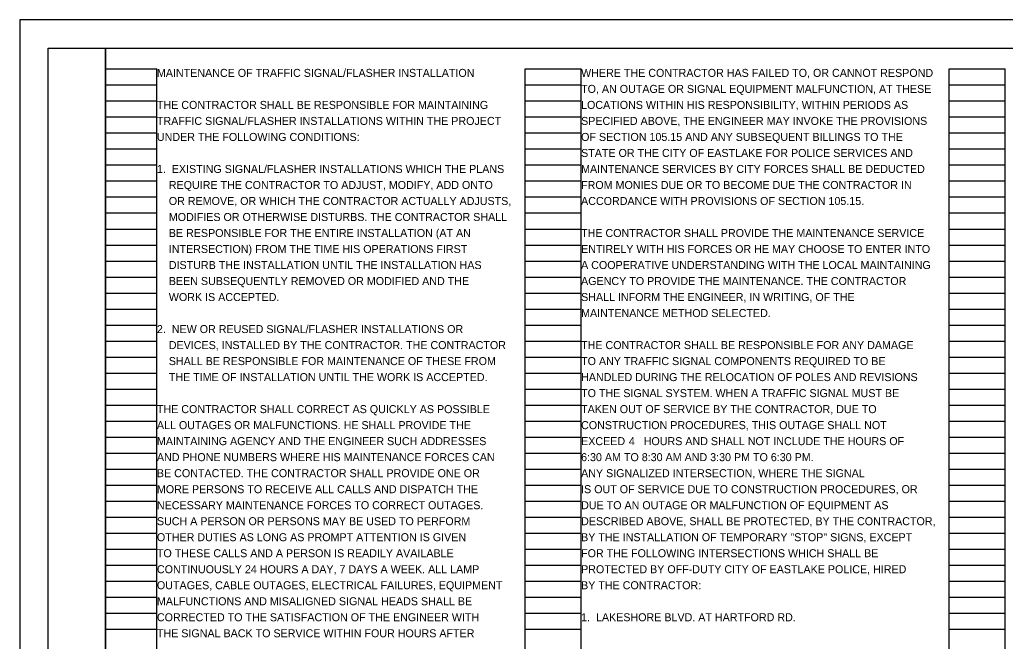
# Model space of a CAD drawing. Extents: x 0 to 34, y 0 to 22.
# Drawn here: x 0 to 17.24, y 11.13 to 22 of the extents above; entities that cross this region are included whole.
import ezdxf

# ---------------------------------------------------------------- set-up
doc = ezdxf.new("R2010")
doc.units = 0
for name, color, linetype in [('SH_Border', 7, 'Continuous'), ('SH_Cut_Line', 7, 'Continuous'), ('SH_Data', 7, 'Continuous'), ('SH_Text', 7, 'Continuous')]:
    doc.layers.add(name, color=color, linetype=linetype)

msp = doc.modelspace()

# ---------------------------------------------------------------- linework, layer by layer
at = {"layer": 'SH_Border'}
for points in [[(0.5, 21.5), (1.5, 21.5), (1.5, 0.5), (0.5, 0.5)], [(1.5, 21.5), (33.5, 21.5), (33.5, 0.5), (1.5, 0.5)]]:
    msp.add_lwpolyline(points, close=True, dxfattribs=at)
at = {"layer": 'SH_Cut_Line'}
msp.add_lwpolyline([(0, 0), (34, 0), (34, 22), (0, 22)], close=True, dxfattribs=at)
at = {"layer": 'SH_Data'}
for p, q in [((1.5, 0.98), (1.5, 21.14)), ((1.5, 21.14), (2.4, 21.14)), ((2.4, 0.98), (2.4, 21.14)), ((8.84, 0.98), (8.84, 21.14)), ((8.84, 21.14), (9.82, 21.14)), ((9.82, 0.98), (9.82, 21.14)), ((16.26, 0.98), (16.26, 21.14)), ((16.26, 21.14), (17.24, 21.14)), ((17.24, 0.98), (17.24, 21.14)), ((1.5, 20.86), (2.4, 20.86)), ((8.84, 20.86), (9.82, 20.86)), ((16.26, 20.86), (17.24, 20.86)), ((1.5, 20.58), (2.4, 20.58)), ((8.84, 20.58), (9.82, 20.58)), ((16.26, 20.58), (17.24, 20.58)), ((1.5, 20.3), (2.4, 20.3)), ((8.84, 20.3), (9.82, 20.3)), ((16.26, 20.3), (17.24, 20.3)), ((1.5, 20.02), (2.4, 20.02)), ((8.84, 20.02), (9.82, 20.02)), ((16.26, 20.02), (17.24, 20.02)), ((1.5, 19.74), (2.4, 19.74)), ((8.84, 19.74), (9.82, 19.74)), ((16.26, 19.74), (17.24, 19.74)), ((1.5, 19.46), (2.4, 19.46)), ((8.84, 19.46), (9.82, 19.46)), ((16.26, 19.46), (17.24, 19.46)), ((1.5, 19.18), (2.4, 19.18)), ((8.84, 19.18), (9.82, 19.18)), ((16.26, 19.18), (17.24, 19.18)), ((1.5, 18.9), (2.4, 18.9)), ((8.84, 18.9), (9.82, 18.9)), ((16.26, 18.9), (17.24, 18.9)), ((1.5, 18.62), (2.4, 18.62)), ((8.84, 18.62), (9.82, 18.62)), ((16.26, 18.62), (17.24, 18.62)), ((1.5, 18.34), (2.4, 18.34)), ((8.84, 18.34), (9.82, 18.34)), ((16.26, 18.34), (17.24, 18.34)), ((1.5, 18.06), (2.4, 18.06)), ((8.84, 18.06), (9.82, 18.06)), ((16.26, 18.06), (17.24, 18.06)), ((1.5, 17.78), (2.4, 17.78)), ((8.84, 17.78), (9.82, 17.78)), ((16.26, 17.78), (17.24, 17.78)), ((1.5, 17.5), (2.4, 17.5)), ((8.84, 17.5), (9.82, 17.5)), ((16.26, 17.5), (17.24, 17.5)), ((1.5, 17.22), (2.4, 17.22)), ((8.84, 17.22), (9.82, 17.22)), ((16.26, 17.22), (17.24, 17.22)), ((1.5, 16.94), (2.4, 16.94)), ((8.84, 16.94), (9.82, 16.94)), ((16.26, 16.94), (17.24, 16.94)), ((1.5, 16.66), (2.4, 16.66)), ((8.84, 16.66), (9.82, 16.66)), ((16.26, 16.66), (17.24, 16.66)), ((1.5, 16.38), (2.4, 16.38)), ((8.84, 16.38), (9.82, 16.38)), ((16.26, 16.38), (17.24, 16.38)), ((1.5, 16.1), (2.4, 16.1)), ((8.84, 16.1), (9.82, 16.1)), ((16.26, 16.1), (17.24, 16.1)), ((1.5, 15.82), (2.4, 15.82)), ((8.84, 15.82), (9.82, 15.82)), ((16.26, 15.82), (17.24, 15.82)), ((1.5, 15.54), (2.4, 15.54)), ((8.84, 15.54), (9.82, 15.54)), ((16.26, 15.54), (17.24, 15.54)), ((1.5, 15.26), (2.4, 15.26)), ((8.84, 15.26), (9.82, 15.26)), ((16.26, 15.26), (17.24, 15.26)), ((1.5, 14.98), (2.4, 14.98)), ((8.84, 14.98), (9.82, 14.98)), ((16.26, 14.98), (17.24, 14.98)), ((1.5, 14.7), (2.4, 14.7)), ((8.84, 14.7), (9.82, 14.7)), ((16.26, 14.7), (17.24, 14.7)), ((1.5, 14.42), (2.4, 14.42)), ((8.84, 14.42), (9.82, 14.42)), ((16.26, 14.42), (17.24, 14.42)), ((1.5, 14.14), (2.4, 14.14)), ((8.84, 14.14), (9.82, 14.14)), ((16.26, 14.14), (17.24, 14.14)), ((1.5, 13.86), (2.4, 13.86)), ((8.84, 13.86), (9.82, 13.86)), ((16.26, 13.86), (17.24, 13.86)), ((1.5, 13.58), (2.4, 13.58)), ((8.84, 13.58), (9.82, 13.58)), ((16.26, 13.58), (17.24, 13.58)), ((1.5, 13.3), (2.4, 13.3)), ((8.84, 13.3), (9.82, 13.3)), ((16.26, 13.3), (17.24, 13.3)), ((1.5, 13.02), (2.4, 13.02)), ((8.84, 13.02), (9.82, 13.02)), ((16.26, 13.02), (17.24, 13.02)), ((1.5, 12.74), (2.4, 12.74)), ((8.84, 12.74), (9.82, 12.74)), ((16.26, 12.74), (17.24, 12.74)), ((1.5, 12.46), (2.4, 12.46)), ((8.84, 12.46), (9.82, 12.46)), ((16.26, 12.46), (17.24, 12.46)), ((1.5, 12.18), (2.4, 12.18)), ((8.84, 12.18), (9.82, 12.18)), ((16.26, 12.18), (17.24, 12.18)), ((1.5, 11.9), (2.4, 11.9)), ((8.84, 11.9), (9.82, 11.9)), ((16.26, 11.9), (17.24, 11.9)), ((1.5, 11.62), (2.4, 11.62)), ((8.84, 11.62), (9.82, 11.62)), ((16.26, 11.62), (17.24, 11.62)), ((1.5, 11.34), (2.4, 11.34)), ((8.84, 11.34), (9.82, 11.34)), ((16.26, 11.34), (17.24, 11.34))]:
    msp.add_line(p, q, dxfattribs=at)

# ---------------------------------------------------------------- texts
at = {"layer": 'SH_Text'}
for s, p in [('MAINTENANCE OF TRAFFIC SIGNAL/FLASHER INSTALLATION', (2.4, 21)), ('WHERE THE CONTRACTOR HAS FAILED TO, OR CANNOT RESPOND', (9.82, 21)), ('TO, AN OUTAGE OR SIGNAL EQUIPMENT MALFUNCTION, AT THESE', (9.82, 20.72)), ('THE CONTRACTOR SHALL BE RESPONSIBLE FOR MAINTAINING', (2.4, 20.44)), ('LOCATIONS WITHIN HIS RESPONSIBILITY, WITHIN PERIODS AS', (9.82, 20.44)), ('TRAFFIC SIGNAL/FLASHER INSTALLATIONS WITHIN THE PROJECT', (2.4, 20.16)), ('SPECIFIED ABOVE, THE ENGINEER MAY INVOKE THE PROVISIONS', (9.82, 20.16)), ('UNDER THE FOLLOWING CONDITIONS:', (2.4, 19.88)), ('OF SECTION 105.15 AND ANY SUBSEQUENT BILLINGS TO THE', (9.82, 19.88)), ('STATE OR THE CITY OF EASTLAKE FOR POLICE SERVICES AND', (9.82, 19.6)), ('1.  EXISTING SIGNAL/FLASHER INSTALLATIONS WHICH THE PLANS', (2.4, 19.32)), ('MAINTENANCE SERVICES BY CITY FORCES SHALL BE DEDUCTED', (9.82, 19.32)), ('    REQUIRE THE CONTRACTOR TO ADJUST, MODIFY, ADD ONTO', (2.4, 19.04)), ('FROM MONIES DUE OR TO BECOME DUE THE CONTRACTOR IN', (9.82, 19.04)), ('    OR REMOVE, OR WHICH THE CONTRACTOR ACTUALLY ADJUSTS,', (2.4, 18.76)), ('ACCORDANCE WITH PROVISIONS OF SECTION 105.15.', (9.82, 18.76)), ('    MODIFIES OR OTHERWISE DISTURBS. THE CONTRACTOR SHALL', (2.4, 18.48)), ('    BE RESPONSIBLE FOR THE ENTIRE INSTALLATION (AT AN', (2.4, 18.2)), ('THE CONTRACTOR SHALL PROVIDE THE MAINTENANCE SERVICE', (9.82, 18.2)), ('    INTERSECTION) FROM THE TIME HIS OPERATIONS FIRST', (2.4, 17.92)), ('ENTIRELY WITH HIS FORCES OR HE MAY CHOOSE TO ENTER INTO', (9.82, 17.92)), ('    DISTURB THE INSTALLATION UNTIL THE INSTALLATION HAS', (2.4, 17.64)), ('A COOPERATIVE UNDERSTANDING WITH THE LOCAL MAINTAINING', (9.82, 17.64)), ('    BEEN SUBSEQUENTLY REMOVED OR MODIFIED AND THE', (2.4, 17.36)), ('AGENCY TO PROVIDE THE MAINTENANCE. THE CONTRACTOR', (9.82, 17.36)), ('    WORK IS ACCEPTED.', (2.4, 17.08)), ('SHALL INFORM THE ENGINEER, IN WRITING, OF THE', (9.82, 17.08)), ('MAINTENANCE METHOD SELECTED.', (9.82, 16.8)), ('2.  NEW OR REUSED SIGNAL/FLASHER INSTALLATIONS OR', (2.4, 16.52)), ('    DEVICES, INSTALLED BY THE CONTRACTOR. THE CONTRACTOR', (2.4, 16.24)), ('THE CONTRACTOR SHALL BE RESPONSIBLE FOR ANY DAMAGE', (9.82, 16.24)), ('    SHALL BE RESPONSIBLE FOR MAINTENANCE OF THESE FROM', (2.4, 15.96)), ('TO ANY TRAFFIC SIGNAL COMPONENTS REQUIRED TO BE', (9.82, 15.96)), ('    THE TIME OF INSTALLATION UNTIL THE WORK IS ACCEPTED.', (2.4, 15.68)), ('HANDLED DURING THE RELOCATION OF POLES AND REVISIONS', (9.82, 15.68)), ('TO THE SIGNAL SYSTEM. WHEN A TRAFFIC SIGNAL MUST BE', (9.82, 15.4)), ('THE CONTRACTOR SHALL CORRECT AS QUICKLY AS POSSIBLE', (2.4, 15.12)), ('TAKEN OUT OF SERVICE BY THE CONTRACTOR, DUE TO', (9.82, 15.12)), ('ALL OUTAGES OR MALFUNCTIONS. HE SHALL PROVIDE THE', (2.4, 14.84)), ('CONSTRUCTION PROCEDURES, THIS OUTAGE SHALL NOT', (9.82, 14.84)), ('MAINTAINING AGENCY AND THE ENGINEER SUCH ADDRESSES', (2.4, 14.56)), ('EXCEED ', (9.82, 14.56)), ('  4  ', (10.552, 14.56)), (' HOURS AND SHALL NOT INCLUDE THE HOURS OF', (10.863, 14.56)), ('AND PHONE NUMBERS WHERE HIS MAINTENANCE FORCES CAN', (2.4, 14.28)), ('6:30 AM TO 8:30 AM AND 3:30 PM TO 6:30 PM.', (9.82, 14.28)), ('BE CONTACTED. THE CONTRACTOR SHALL PROVIDE ONE OR', (2.4, 14)), ('ANY SIGNALIZED INTERSECTION, WHERE THE SIGNAL', (9.82, 14)), ('MORE PERSONS TO RECEIVE ALL CALLS AND DISPATCH THE', (2.4, 13.72)), ('IS OUT OF SERVICE DUE TO CONSTRUCTION PROCEDURES, OR', (9.82, 13.72)), ('NECESSARY MAINTENANCE FORCES TO CORRECT OUTAGES.', (2.4, 13.44)), ('DUE TO AN OUTAGE OR MALFUNCTION OF EQUIPMENT AS', (9.82, 13.44)), ('SUCH A PERSON OR PERSONS MAY BE USED TO PERFORM', (2.4, 13.16)), ('DESCRIBED ABOVE, SHALL BE PROTECTED, BY THE CONTRACTOR,', (9.82, 13.16)), ('OTHER DUTIES AS LONG AS PROMPT ATTENTION IS GIVEN', (2.4, 12.88)), ('BY THE INSTALLATION OF TEMPORARY "STOP" SIGNS, EXCEPT', (9.82, 12.88)), ('TO THESE CALLS AND A PERSON IS READILY AVAILABLE', (2.4, 12.6)), ('FOR THE FOLLOWING INTERSECTIONS WHICH SHALL BE', (9.82, 12.6)), ('CONTINUOUSLY 24 HOURS A DAY, 7 DAYS A WEEK. ALL LAMP', (2.4, 12.32)), ('PROTECTED BY OFF-DUTY CITY OF EASTLAKE POLICE, HIRED', (9.82, 12.32)), ('OUTAGES, CABLE OUTAGES, ELECTRICAL FAILURES, EQUIPMENT', (2.4, 12.04)), ('BY THE CONTRACTOR:', (9.82, 12.04)), ('MALFUNCTIONS AND MISALIGNED SIGNAL HEADS SHALL BE', (2.4, 11.76)), ('CORRECTED TO THE SATISFACTION OF THE ENGINEER WITH', (2.4, 11.48)), ('1.  LAKESHORE BLVD. AT HARTFORD RD.', (9.82, 11.48)), ('THE SIGNAL BACK TO SERVICE WITHIN FOUR HOURS AFTER', (2.4, 11.2))]:
    msp.add_text(s, height=0.14, dxfattribs=at).set_placement(p)

doc.saveas('drawing.dxf')
